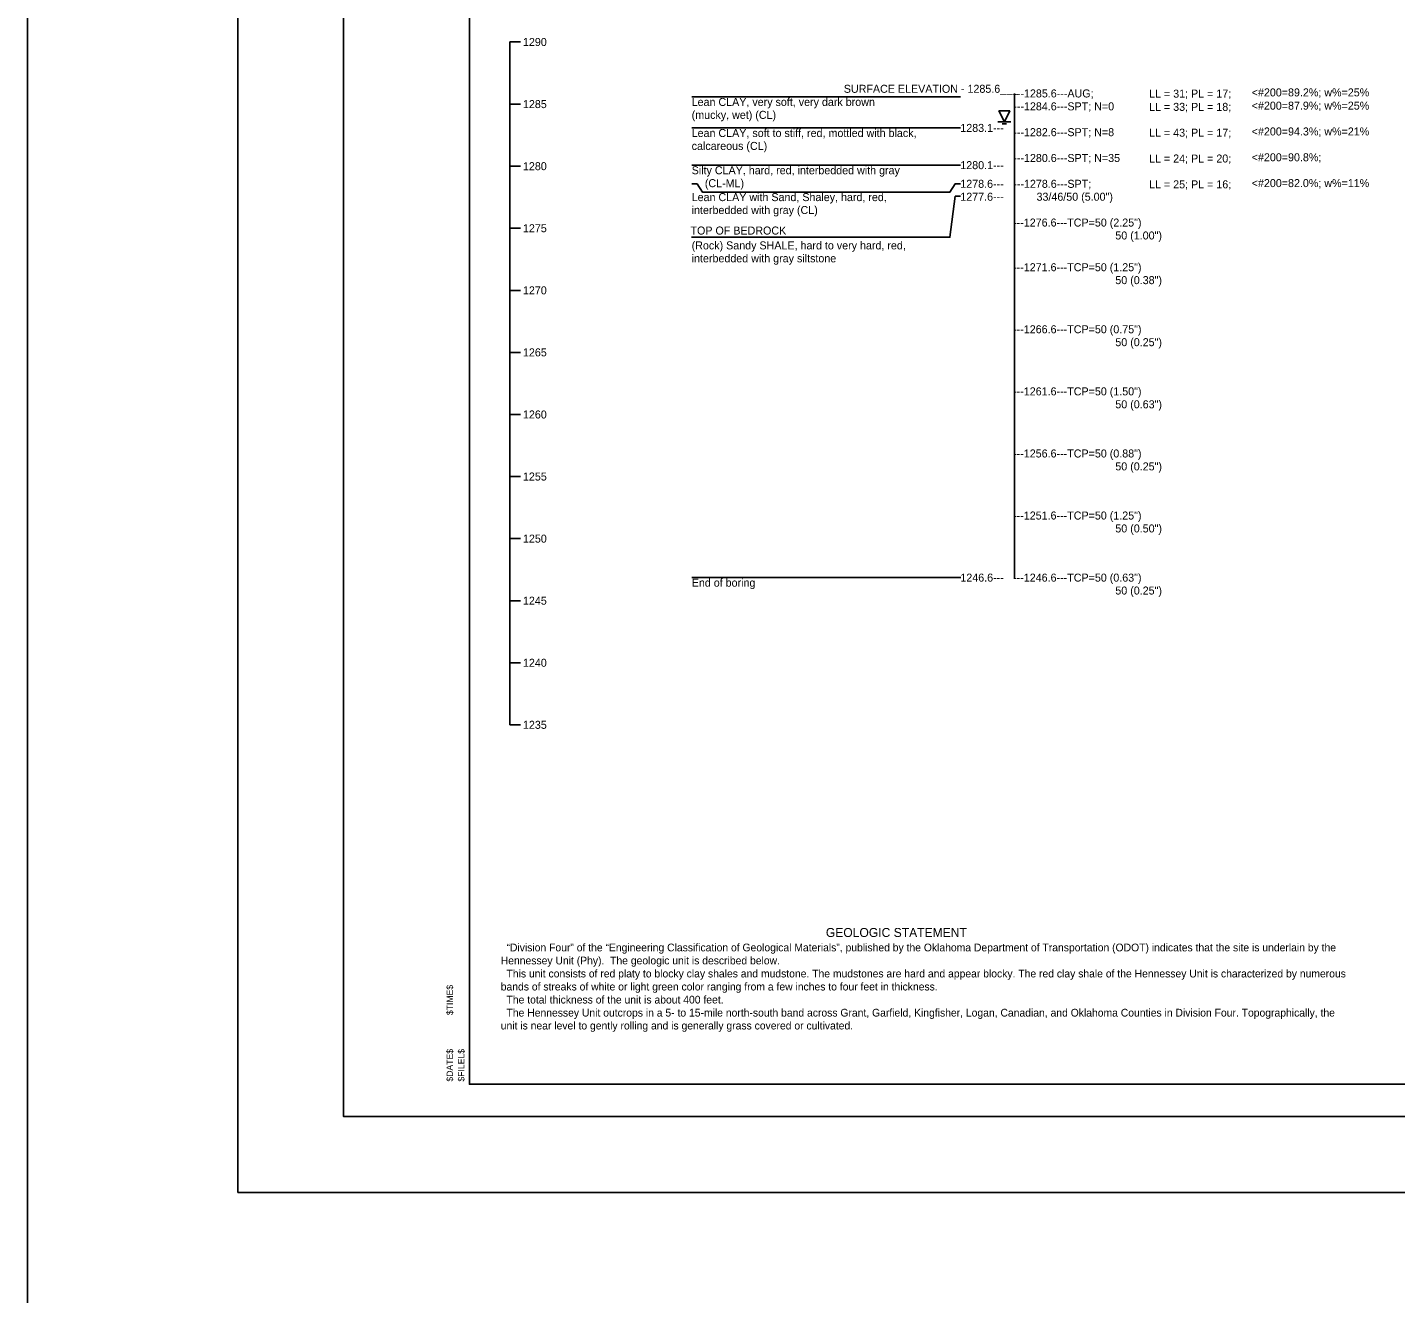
# Model space of a CAD drawing. Extents: x 2150161.5 to 2150203.1, y 143779.5 to 143868.5.
# Drawn here: x 2150161.53 to 2150182.73, y 143834.58 to 143854.19 of the extents above; entities that cross this region are included whole.
import ezdxf

# ---------------------------------------------------------------- set-up
doc = ezdxf.new("R2010")
doc.units = 0
for name, color, linetype in [('Default', 7, 'Continuous'), ('S', 7, 'Continuous'), ('SHT_Plot_Shape_Full', 7, 'Continuous'), ('SHT_Plot_Shape_Half', 7, 'Continuous'), ('SHT_Plot_Stamp', 7, 'Continuous'), ('SHT_Sheet_Border', 7, 'Continuous'), ('Text', 7, 'Continuous')]:
    doc.layers.add(name, color=color, linetype=linetype)

# ---------------------------------------------------------------- blocks, each defined once
blk = doc.blocks.new('Stamp_Plot_Stamp')
at = {"layer": 'SHT_Plot_Stamp'}
for s, p in [('$TIME$', (1.695, 1.572)), ('$DATE$', (1.695, 0.542)), ('$FILEL$', (1.873, 0.542))]:
    blk.add_text(s, height=0.1, rotation=90, dxfattribs=at).set_placement(p)
blk = doc.blocks.new('DGRFC_WTLEV1')
at = {"layer": 'Default'}
for points in [[(-0.0127, 0), (0.0127, 0)], [(0, 0), (0.0106, 0.0212), (-0.0106, 0.0212), (0, 0)], [(-0.0042, -0.0042), (0.0042, -0.0042)]]:
    blk.add_lwpolyline(points, dxfattribs=at)

msp = doc.modelspace()

# ---------------------------------------------------------------- linework, layer by layer
at = {"layer": 'Default'}
msp.add_line((2150169.005, 143843.388), (2150169.005, 143853.965), dxfattribs=at)
for points in [[(2150169.005, 143853.965), (2150169.171, 143853.965)], [(2150171.822, 143853.115), (2150175.989, 143853.115)], [(2150176.823, 143853.165), (2150176.823, 143845.66)], [(2150169.005, 143853.003), (2150169.171, 143853.003)], [(2150171.822, 143852.634), (2150175.989, 143852.634)], [(2150169.005, 143852.041), (2150169.171, 143852.041)], [(2150171.822, 143852.057), (2150175.989, 143852.057)], [(2150171.822, 143851.768), (2150171.905, 143851.768), (2150171.989, 143851.64), (2150175.822, 143851.64), (2150175.905, 143851.768), (2150175.989, 143851.768)], [(2150171.818, 143850.941), (2150175.822, 143850.941), (2150175.905, 143851.576), (2150175.989, 143851.576)], [(2150169.005, 143851.08), (2150169.171, 143851.08)], [(2150169.005, 143850.118), (2150169.171, 143850.118)], [(2150169.005, 143849.157), (2150169.171, 143849.157)], [(2150169.005, 143848.195), (2150169.171, 143848.195)], [(2150169.005, 143847.234), (2150169.171, 143847.234)], [(2150169.005, 143846.272), (2150169.171, 143846.272)], [(2150171.823, 143845.668), (2150175.99, 143845.668)], [(2150169.005, 143845.311), (2150169.171, 143845.311)], [(2150169.005, 143845.311), (2150169.171, 143845.311)], [(2150169.005, 143844.349), (2150169.171, 143844.349)], [(2150169.005, 143844.349), (2150169.171, 143844.349)], [(2150169.005, 143843.388), (2150169.171, 143843.388)], [(2150169.005, 143843.388), (2150169.171, 143843.388)]]:
    msp.add_lwpolyline(points, dxfattribs=at)
at = {"layer": 'S'}
msp.add_lwpolyline([(2150161.53, 143868.477), (2150203.071, 143868.477), (2150203.071, 143779.536), (2150161.53, 143779.536)], close=True, dxfattribs=at)
at = {"layer": 'SHT_Plot_Shape_Full'}
msp.add_lwpolyline([(2150164.792, 143860.145), (2150200.792, 143860.145), (2150200.792, 143836.145), (2150164.792, 143836.145)], close=True, dxfattribs=at)
at = {"layer": 'SHT_Plot_Shape_Half'}
msp.add_lwpolyline([(2150166.429, 143859.32), (2150200.429, 143859.32), (2150200.429, 143837.32), (2150166.429, 143837.32)], close=True, dxfattribs=at)
at = {"layer": 'SHT_Sheet_Border'}
msp.add_lwpolyline([(2150199.879, 143837.82), (2150168.379, 143837.82), (2150168.379, 143858.82), (2150199.879, 143858.82)], close=True, dxfattribs=at)

# ---------------------------------------------------------------- block references
at = {"layer": 'Default', "xscale": 7.873999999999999, "yscale": 7.873999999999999}
msp.add_blockref('DGRFC_WTLEV1', (2150176.667, 143852.73), dxfattribs=at)
at = {"layer": 'SHT_Plot_Stamp'}
msp.add_blockref('Stamp_Plot_Stamp', (2150166.429, 143837.32), dxfattribs=at)

# ---------------------------------------------------------------- texts
at = {"layer": 'Default'}
for s, p in [('1290', (2150169.208, 143853.903)), ('SURFACE ELEVATION - 1285.6___', (2150174.179, 143853.178)), ('---1285.6---AUG;', (2150176.805, 143853.106)), ('<#200=89.2%; w%=25%', (2150180.499, 143853.122)), ('1285', (2150169.208, 143852.941)), ('Lean CLAY, very soft, very dark brown', (2150171.822, 143852.974)), ('---1284.6---SPT; N=0', (2150176.805, 143852.906)), ('LL = 31; PL = 17;', (2150178.909, 143853.103)), ('LL = 33; PL = 18;', (2150178.909, 143852.898)), ('<#200=87.9%; w%=25%', (2150180.499, 143852.917)), ('(mucky, wet) (CL)', (2150171.822, 143852.774)), ('Lean CLAY, soft to stiff, red, mottled with black,', (2150171.822, 143852.493)), ('1283.1---', (2150175.984, 143852.572)), ('---1282.6---SPT; N=8', (2150176.805, 143852.506)), ('LL = 43; PL = 17;', (2150178.909, 143852.498)), ('<#200=94.3%; w%=21%', (2150180.499, 143852.517)), ('calcareous (CL)', (2150171.822, 143852.293)), ('---1280.6---SPT; N=35', (2150176.805, 143852.106)), ('LL = 24; PL = 20;', (2150178.909, 143852.098)), ('<#200=90.8%;', (2150180.499, 143852.117)), ('1280', (2150169.208, 143851.979)), ('Silty CLAY, hard, red, interbedded with gray', (2150171.822, 143851.916)), ('1280.1---', (2150175.984, 143851.995)), ('(CL-ML)', (2150172.026, 143851.716)), ('1278.6---', (2150175.984, 143851.706)), ('---1278.6---SPT;', (2150176.805, 143851.706)), ('LL = 25; PL = 16;', (2150178.909, 143851.698)), ('<#200=82.0%; w%=11%', (2150180.499, 143851.717)), ('Lean CLAY with Sand, Shaley, hard, red,', (2150171.822, 143851.5)), ('1277.6---', (2150175.984, 143851.506)), ('33/46/50 (5.00")', (2150177.165, 143851.506)), ('interbedded with gray (CL)', (2150171.822, 143851.3)), ('1275', (2150169.208, 143851.018)), ('---1276.6---TCP=50 (2.25")', (2150176.802, 143851.106)), ('TOP OF BEDROCK', (2150171.804, 143850.982)), ('50 (1.00")', (2150178.386, 143850.906)), ('(Rock) Sandy SHALE, hard to very hard, red,', (2150171.822, 143850.752)), ('interbedded with gray siltstone', (2150171.822, 143850.552)), ('---1271.6---TCP=50 (1.25")', (2150176.802, 143850.414)), ('50 (0.38")', (2150178.386, 143850.214)), ('1270', (2150169.208, 143850.056)), ('---1266.6---TCP=50 (0.75")', (2150176.802, 143849.453)), ('1265', (2150169.208, 143849.095)), ('50 (0.25")', (2150178.386, 143849.253)), ('---1261.6---TCP=50 (1.50")', (2150176.802, 143848.491)), ('50 (0.63")', (2150178.386, 143848.291)), ('1260', (2150169.208, 143848.133)), ('---1256.6---TCP=50 (0.88")', (2150176.802, 143847.529)), ('1255', (2150169.208, 143847.172)), ('50 (0.25")', (2150178.386, 143847.329)), ('---1251.6---TCP=50 (1.25")', (2150176.802, 143846.568)), ('50 (0.50")', (2150178.386, 143846.368)), ('1250', (2150169.208, 143846.21)), ('End of boring', (2150171.823, 143845.528)), ('1246.6---', (2150175.985, 143845.606)), ('---1246.6---TCP=50 (0.63")', (2150176.802, 143845.606)), ('50 (0.25")', (2150178.386, 143845.406)), ('1245', (2150169.208, 143845.249)), ('1240', (2150169.208, 143844.287)), ('1235', (2150169.208, 143843.326))]:
    msp.add_text(s, height=0.124, dxfattribs=at).set_placement(p)
at = {"layer": 'Text'}
for s, height, p in [('GEOLOGIC STATEMENT', 0.14, (2150173.901, 143840.101)), ('  “Division Four” of the “Engineering Classification of Geological Materials”, published by the Oklahoma Department of Transportation (ODOT) indicates that the site is underlain by the ', 0.12, (2150168.864, 143839.879)), ('Hennessey Unit (Phy).  The geologic unit is described below. ', 0.12, (2150168.864, 143839.677)), ('  This unit consists of red platy to blocky clay shales and mudstone. The mudstones are hard and appear blocky. The red clay shale of the Hennessey Unit is characterized by numerous ', 0.12, (2150168.864, 143839.475)), ('bands of streaks of white or light green color ranging from a few inches to four feet in thickness. ', 0.12, (2150168.864, 143839.273)), ('  The total thickness of the unit is about 400 feet.', 0.12, (2150168.864, 143839.071)), ('  The Hennessey Unit outcrops in a 5- to 15-mile north-south band across Grant, Garfield, Kingfisher, Logan, Canadian, and Oklahoma Counties in Division Four. Topographically, the ', 0.12, (2150168.864, 143838.869)), ('unit is near level to gently rolling and is generally grass covered or cultivated.', 0.12, (2150168.864, 143838.669))]:
    msp.add_text(s, height=height, dxfattribs=at).set_placement(p)

doc.saveas('drawing.dxf')
